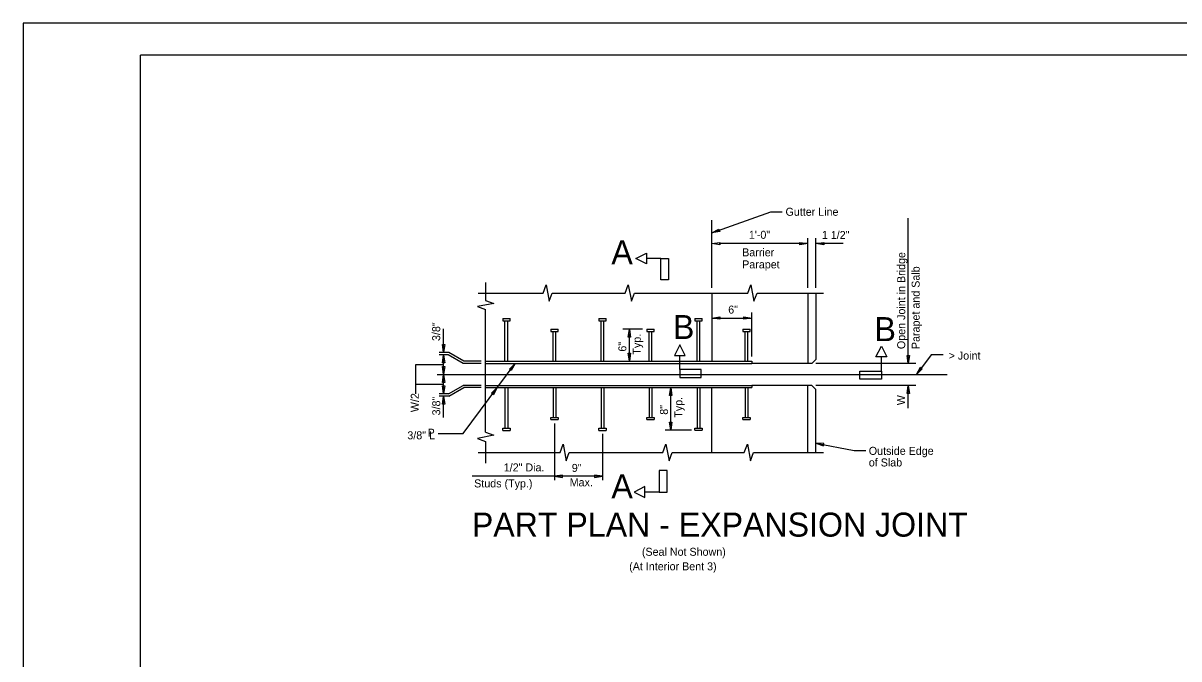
# Model space of a CAD drawing. Extents: x -125.5 to -89.4, y -5.1 to 16.9.
# Drawn here: x -125.53 to -107.48, y 7.01 to 16.93 of the extents above; entities that cross this region are included whole.
import ezdxf

# ---------------------------------------------------------------- set-up
doc = ezdxf.new("R2010")
doc.units = 0
for name, color, linetype in [('BR_AUTO DIMENSION', 7, 'Continuous'), ('BR_BORDER LINES', 7, 'Continuous'), ('BR_CENTER LINES', 7, 'Continuous'), ('BR_CONCRETE', 7, 'Continuous'), ('BR_STRUCTURAL STEEL', 7, 'Continuous'), ('BR_TABLE LINES', 7, 'Continuous'), ('BR_TEXT', 7, 'Continuous'), ('Level 31', 7, 'Continuous')]:
    doc.layers.add(name, color=color, linetype=linetype)

msp = doc.modelspace()

# ---------------------------------------------------------------- linework, layer by layer
at = {"layer": 'BR_AUTO DIMENSION'}
for p, q in [((-114.775, 13.659), (-113.854, 13.987)), ((-113.854, 13.987), (-113.674, 13.987)), ((-114.775, 12.801), (-114.775, 13.861)), ((-111.707, 11.623), (-111.707, 13.89)), ((-113.275, 13.242), (-113.275, 13.575)), ((-113.15, 12.8), (-113.15, 13.575)), ((-113.275, 13.493), (-114.661, 13.493)), ((-113.275, 12.8), (-113.275, 13.419)), ((-112.721, 13.493), (-113.15, 13.493)), ((-113.275, 12.8), (-113.275, 12.932)), ((-114.775, 12.331), (-114.148, 12.331)), ((-114.148, 11.733), (-114.148, 12.416)), ((-118.966, 11.791), (-118.966, 12.162)), ((-115.859, 12.156), (-116.165, 12.156)), ((-116.061, 11.656), (-116.061, 12.089)), ((-118.883, 11.791), (-119.033, 11.791)), ((-118.892, 11.757), (-119.033, 11.757)), ((-118.966, 11.451), (-118.966, 11.757)), ((-118.657, 11.623), (-118.892, 11.757)), ((-118.648, 11.656), (-118.883, 11.791)), ((-111.351, 11.755), (-111.576, 11.451)), ((-111.16, 11.755), (-111.351, 11.755)), ((-119.399, 11.607), (-118.966, 11.607)), ((-119.399, 11.15), (-119.399, 11.607)), ((-118.66, 10.528), (-117.847, 11.623)), ((-118.376, 11.623), (-118.657, 11.623)), ((-118.376, 11.656), (-118.648, 11.656)), ((-111.586, 11.623), (-113.15, 11.623)), ((-118.966, 11.146), (-118.966, 11.451)), ((-119.399, 11.301), (-118.966, 11.301)), ((-118.89, 11.146), (-118.657, 11.279)), ((-118.881, 11.112), (-118.648, 11.245)), ((-118.376, 11.279), (-118.657, 11.279)), ((-118.376, 11.245), (-118.648, 11.245)), ((-115.417, 10.647), (-115.417, 11.245)), ((-111.586, 11.279), (-113.15, 11.279)), ((-111.707, 10.922), (-111.707, 11.279)), ((-118.89, 11.146), (-119.033, 11.146)), ((-118.881, 11.112), (-119.033, 11.112)), ((-118.966, 10.777), (-118.966, 11.112)), ((-117.233, 10.687), (-117.233, 9.799)), ((-119.048, 10.528), (-118.66, 10.528)), ((-116.483, 10.523), (-116.483, 9.799)), ((-115.095, 10.579), (-115.505, 10.579)), ((-113.15, 10.378), (-112.553, 10.264)), ((-112.553, 10.264), (-112.372, 10.264)), ((-116.483, 9.861), (-118.516, 9.861)), ((-117.233, 9.861), (-117.233, 9.861))]:
    msp.add_line(p, q, dxfattribs=at)
for points in [[(-114.651, 13.684), (-114.775, 13.659), (-114.664, 13.719)], [(-114.65, 13.474), (-114.775, 13.493), (-114.65, 13.511)], [(-113.4, 13.511), (-113.275, 13.493), (-113.4, 13.474)], [(-113.025, 13.474), (-113.15, 13.493), (-113.025, 13.511)], [(-114.65, 12.313), (-114.775, 12.331), (-114.65, 12.35)], [(-114.273, 12.35), (-114.148, 12.331), (-114.273, 12.313)], [(-114.273, 12.35), (-114.148, 12.331), (-114.273, 12.313)], [(-116.08, 12.031), (-116.061, 12.156), (-116.043, 12.031)], [(-116.08, 12.031), (-116.061, 12.156), (-116.043, 12.031)], [(-118.947, 11.916), (-118.966, 11.791), (-118.984, 11.916)], [(-118.984, 11.632), (-118.966, 11.757), (-118.947, 11.632)], [(-116.043, 11.781), (-116.061, 11.656), (-116.08, 11.781)], [(-111.688, 11.748), (-111.707, 11.623), (-111.725, 11.748)], [(-118.947, 11.576), (-118.966, 11.451), (-118.984, 11.576)], [(-117.937, 11.533), (-117.847, 11.623), (-117.907, 11.511)], [(-111.487, 11.54), (-111.576, 11.451), (-111.517, 11.563)], [(-118.984, 11.326), (-118.966, 11.451), (-118.947, 11.326)], [(-118.947, 11.271), (-118.966, 11.146), (-118.984, 11.271)], [(-118.218, 11.156), (-118.128, 11.245), (-118.187, 11.134)], [(-115.436, 11.12), (-115.417, 11.245), (-115.398, 11.12)], [(-111.725, 11.154), (-111.707, 11.279), (-111.688, 11.154)], [(-118.984, 10.987), (-118.966, 11.112), (-118.947, 10.987)], [(-115.398, 10.704), (-115.417, 10.579), (-115.436, 10.704)], [(-113.023, 10.373), (-113.15, 10.378), (-113.03, 10.336)], [(-117.108, 9.88), (-117.233, 9.861), (-117.108, 9.843)], [(-116.608, 9.843), (-116.483, 9.861), (-116.608, 9.88)], [(-116.608, 9.843), (-116.483, 9.861), (-116.608, 9.88)]]:
    msp.add_lwpolyline(points, close=True, dxfattribs=at)
at = {"layer": 'BR_BORDER LINES'}
for p in [(-90.033, 16.434), (-123.699, -4.566)]:
    msp.add_line(p, (-123.699, 16.434), dxfattribs=at)
at = {"layer": 'BR_CENTER LINES'}
for p, q in [((-118.309, 12.885), (-118.309, 12.607)), ((-118.425, 12.72), (-117.412, 12.72)), ((-117.268, 12.72), (-116.128, 12.72)), ((-115.983, 12.72), (-114.214, 12.72)), ((-114.069, 12.72), (-113.029, 12.72)), ((-118.309, 10.549), (-118.309, 12.462)), ((-119.064, 11.451), (-118.83, 11.451)), ((-118.83, 11.451), (-117.913, 11.451)), ((-117.913, 11.451), (-111.098, 11.451)), ((-118.309, 10.404), (-118.309, 10.066)), ((-118.425, 10.231), (-117.145, 10.231)), ((-117.001, 10.231), (-115.539, 10.231)), ((-115.394, 10.231), (-114.268, 10.231)), ((-114.124, 10.231), (-113.029, 10.231))]:
    msp.add_line(p, q, dxfattribs=at)
for points in [[(-117.412, 12.72), (-117.364, 12.849), (-117.316, 12.592), (-117.268, 12.72)], [(-116.128, 12.72), (-116.08, 12.849), (-116.031, 12.592), (-115.983, 12.72)], [(-114.214, 12.72), (-114.166, 12.849), (-114.118, 12.592), (-114.069, 12.72)], [(-118.309, 12.607), (-118.18, 12.559), (-118.437, 12.51), (-118.309, 12.462)], [(-118.309, 10.549), (-118.18, 10.5), (-118.437, 10.452), (-118.309, 10.404)], [(-117.145, 10.231), (-117.097, 10.36), (-117.049, 10.103), (-117.001, 10.231)], [(-115.539, 10.231), (-115.491, 10.36), (-115.443, 10.103), (-115.394, 10.231)], [(-114.268, 10.231), (-114.22, 10.36), (-114.172, 10.103), (-114.124, 10.231)]]:
    msp.add_lwpolyline(points, dxfattribs=at)
at = {"layer": 'BR_CONCRETE'}
for p, q in [((-114.775, 12.72), (-114.775, 11.656)), ((-113.275, 12.72), (-113.275, 11.623)), ((-113.15, 12.72), (-113.15, 11.686)), ((-113.213, 11.623), (-114.148, 11.623)), ((-113.15, 11.686), (-113.213, 11.623)), ((-114.775, 10.231), (-114.775, 11.245)), ((-113.212, 11.279), (-114.148, 11.279)), ((-113.275, 10.231), (-113.275, 11.279)), ((-113.15, 11.216), (-113.212, 11.279)), ((-113.15, 10.231), (-113.15, 11.216))]:
    msp.add_line(p, q, dxfattribs=at)
at = {"layer": 'BR_STRUCTURAL STEEL'}
for p, q in [((-118.039, 12.323), (-117.926, 12.323)), ((-118.039, 12.323), (-118.039, 12.289)), ((-118.039, 12.289), (-117.926, 12.289)), ((-118.006, 12.323), (-117.994, 12.323)), ((-118.006, 11.656), (-118.006, 12.289)), ((-117.96, 11.656), (-117.96, 12.289)), ((-117.926, 12.289), (-117.926, 12.323)), ((-116.539, 12.323), (-116.426, 12.323)), ((-116.539, 12.323), (-116.539, 12.289)), ((-116.539, 12.289), (-116.426, 12.289)), ((-116.506, 12.323), (-116.494, 12.323)), ((-116.506, 11.656), (-116.506, 12.289)), ((-116.46, 11.656), (-116.46, 12.289)), ((-116.426, 12.289), (-116.426, 12.323)), ((-115.039, 12.323), (-114.926, 12.323)), ((-115.039, 12.323), (-115.039, 12.289)), ((-115.039, 12.289), (-114.926, 12.289)), ((-115.006, 11.656), (-115.006, 12.289)), ((-115.005, 12.323), (-114.993, 12.323)), ((-114.96, 11.656), (-114.96, 12.289)), ((-114.926, 12.289), (-114.926, 12.323)), ((-117.289, 12.156), (-117.176, 12.156)), ((-117.289, 12.156), (-117.289, 12.123)), ((-117.289, 12.123), (-117.176, 12.123)), ((-117.255, 11.656), (-117.255, 12.123)), ((-117.21, 11.656), (-117.21, 12.123)), ((-117.176, 12.123), (-117.176, 12.156)), ((-115.79, 12.156), (-115.677, 12.156)), ((-115.79, 12.156), (-115.79, 12.123)), ((-115.79, 12.123), (-115.677, 12.123)), ((-115.756, 11.656), (-115.756, 12.123)), ((-115.711, 11.656), (-115.711, 12.123)), ((-115.677, 12.123), (-115.677, 12.156)), ((-114.29, 12.156), (-114.177, 12.156)), ((-114.29, 12.156), (-114.29, 12.123)), ((-114.29, 12.123), (-114.177, 12.123)), ((-114.256, 11.656), (-114.256, 12.123)), ((-114.211, 11.656), (-114.211, 12.123)), ((-114.177, 12.123), (-114.177, 12.156)), ((-118.309, 11.656), (-118.129, 11.656)), ((-118.309, 11.623), (-114.775, 11.623)), ((-118.129, 11.656), (-114.775, 11.656)), ((-114.775, 11.656), (-114.148, 11.656)), ((-114.775, 11.623), (-114.148, 11.623)), ((-114.148, 11.656), (-114.148, 11.623)), ((-118.309, 11.279), (-114.775, 11.279)), ((-118.309, 11.245), (-114.775, 11.245)), ((-118.006, 11.245), (-118.006, 10.612)), ((-117.96, 11.245), (-117.96, 10.612)), ((-117.255, 11.245), (-117.255, 10.779)), ((-117.21, 11.245), (-117.21, 10.779)), ((-116.506, 11.245), (-116.506, 10.612)), ((-116.46, 11.245), (-116.46, 10.612)), ((-115.756, 11.246), (-115.756, 10.779)), ((-115.711, 11.246), (-115.711, 10.779)), ((-115.52, 11.245), (-114.775, 11.245)), ((-115.006, 11.246), (-115.006, 10.613)), ((-114.96, 11.246), (-114.96, 10.613)), ((-114.775, 11.279), (-114.148, 11.279)), ((-114.775, 11.245), (-114.148, 11.245)), ((-114.256, 11.246), (-114.256, 10.779)), ((-114.211, 11.246), (-114.211, 10.779)), ((-114.148, 11.279), (-114.148, 11.245)), ((-117.289, 10.745), (-117.289, 10.779)), ((-117.289, 10.779), (-117.176, 10.779)), ((-117.289, 10.745), (-117.176, 10.745)), ((-117.255, 10.745), (-117.244, 10.745)), ((-117.176, 10.779), (-117.176, 10.745)), ((-115.79, 10.746), (-115.79, 10.779)), ((-115.79, 10.779), (-115.677, 10.779)), ((-115.79, 10.746), (-115.677, 10.746)), ((-115.677, 10.779), (-115.677, 10.746)), ((-114.29, 10.746), (-114.29, 10.779)), ((-114.29, 10.779), (-114.177, 10.779)), ((-114.29, 10.746), (-114.177, 10.746)), ((-114.177, 10.779), (-114.177, 10.746)), ((-118.039, 10.578), (-118.039, 10.612)), ((-118.039, 10.612), (-117.926, 10.612)), ((-118.039, 10.578), (-117.926, 10.578)), ((-118.006, 10.578), (-117.994, 10.578)), ((-117.926, 10.612), (-117.926, 10.578)), ((-116.539, 10.578), (-116.539, 10.612)), ((-116.539, 10.612), (-116.426, 10.612)), ((-116.539, 10.578), (-116.426, 10.578)), ((-116.506, 10.578), (-116.494, 10.578)), ((-116.426, 10.612), (-116.426, 10.578)), ((-115.039, 10.579), (-115.039, 10.613)), ((-115.039, 10.613), (-114.926, 10.613)), ((-115.039, 10.579), (-114.926, 10.579)), ((-115.005, 10.579), (-114.993, 10.579)), ((-114.926, 10.613), (-114.926, 10.579))]:
    msp.add_line(p, q, dxfattribs=at)
at = {"layer": 'BR_TABLE LINES'}
for p, q in [((-115.573, 13.261), (-115.795, 13.261)), ((-115.275, 11.526), (-115.275, 11.748)), ((-112.127, 11.502), (-112.127, 11.724)), ((-115.597, 9.615), (-115.819, 9.615))]:
    msp.add_line(p, q, dxfattribs=at)
for points in [[(-115.795, 13.178), (-115.962, 13.261), (-115.795, 13.345)], [(-115.451, 12.928), (-115.573, 12.928), (-115.573, 13.261), (-115.451, 13.261)], [(-115.192, 11.748), (-115.275, 11.915), (-115.358, 11.748)], [(-112.211, 11.724), (-112.127, 11.89), (-112.044, 11.724)], [(-114.942, 11.403), (-114.942, 11.526), (-115.275, 11.526), (-115.275, 11.403)], [(-112.461, 11.379), (-112.461, 11.502), (-112.127, 11.502), (-112.127, 11.379)], [(-115.475, 9.949), (-115.597, 9.949), (-115.597, 9.615), (-115.475, 9.615)], [(-115.819, 9.699), (-115.986, 9.615), (-115.819, 9.532)]]:
    msp.add_lwpolyline(points, close=True, dxfattribs=at)
at = {"layer": 'Level 31'}
msp.add_line((-89.533, 16.934), (-125.533, 16.934), dxfattribs=at)
msp.add_lwpolyline([(-125.533, 16.934), (-125.533, -5.066), (-89.533, -5.066), (-89.533, 16.934)], dxfattribs=at)

# ---------------------------------------------------------------- texts
at = {"layer": 'BR_TEXT'}
for s, height, p in [('Gutter Line', 0.125, (-113.624, 13.927)), ('A', 0.375, (-116.344, 13.171)), ('1\'-0"', 0.125, (-114.197, 13.568)), ('1 1/2"', 0.125, (-113.056, 13.565)), ('Barrier', 0.125, (-114.301, 13.294)), ('Parapet', 0.125, (-114.301, 13.106)), ('6"', 0.125, (-114.519, 12.4)), ('B', 0.375, (-115.383, 12.003)), ('B', 0.375, (-112.234, 11.97)), ('> Joint', 0.125, (-111.076, 11.682)), ('3/8" L', 0.125, (-119.531, 10.438)), ('P', 0.125, (-119.214, 10.478)), ('Outside Edge', 0.125, (-112.323, 10.195)), ('of Slab', 0.125, (-112.323, 10.014)), ('1/2" Dia.', 0.125, (-118.025, 9.937)), ('9" ', 0.125, (-116.962, 9.929)), ('Studs (Typ.)', 0.125, (-118.487, 9.687)), ('Max.', 0.125, (-116.995, 9.704)), ('A', 0.375, (-116.344, 9.518)), ('PART PLAN - EXPANSION JOINT', 0.375, (-118.523, 8.919)), ('(Seal Not Shown)', 0.125, (-115.867, 8.62)), ('(At Interior Bent 3)', 0.125, (-116.066, 8.393))]:
    msp.add_text(s, height=height, dxfattribs=at).set_placement(p)
for s, p in [('Open Joint in Bridge', (-111.754, 11.846)), ('Parapet and Salb', (-111.529, 11.846)), ('3/8"', (-119.018, 11.972)), (' 6"', (-116.11, 11.76)), ('Typ.', (-115.885, 11.76)), ('W/2', (-119.352, 10.862)), ('3/8"', (-119.017, 10.811)), ('Typ.', (-115.235, 10.775)), ('W', (-111.758, 10.97)), (' 8"', (-115.46, 10.775))]:
    msp.add_text(s, height=0.125, rotation=90, dxfattribs=at).set_placement(p)

doc.saveas('drawing.dxf')
